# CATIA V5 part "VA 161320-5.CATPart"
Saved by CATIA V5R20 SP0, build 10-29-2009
Part number: VA 161320-5
Revision: ANY
Definition: UNKNOWN
Nomenclature: VA 161320-5
Source: Unknown
Bounding box of the stored display mesh (mm): x -6.5 to 6.5, y 0.2 to 4.2, z -6.337 to 6.337
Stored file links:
  C:\Users\Utente\Desktop\IO LAVORO\3D X SITO CF\CUMSA\3D files VA\VA 161320\VA 161320-5.CATPart
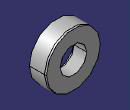
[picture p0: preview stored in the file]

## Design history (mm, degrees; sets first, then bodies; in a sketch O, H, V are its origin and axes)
Body1 "Cortar-Extruir1" (main body)
  Solid1: solid without history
